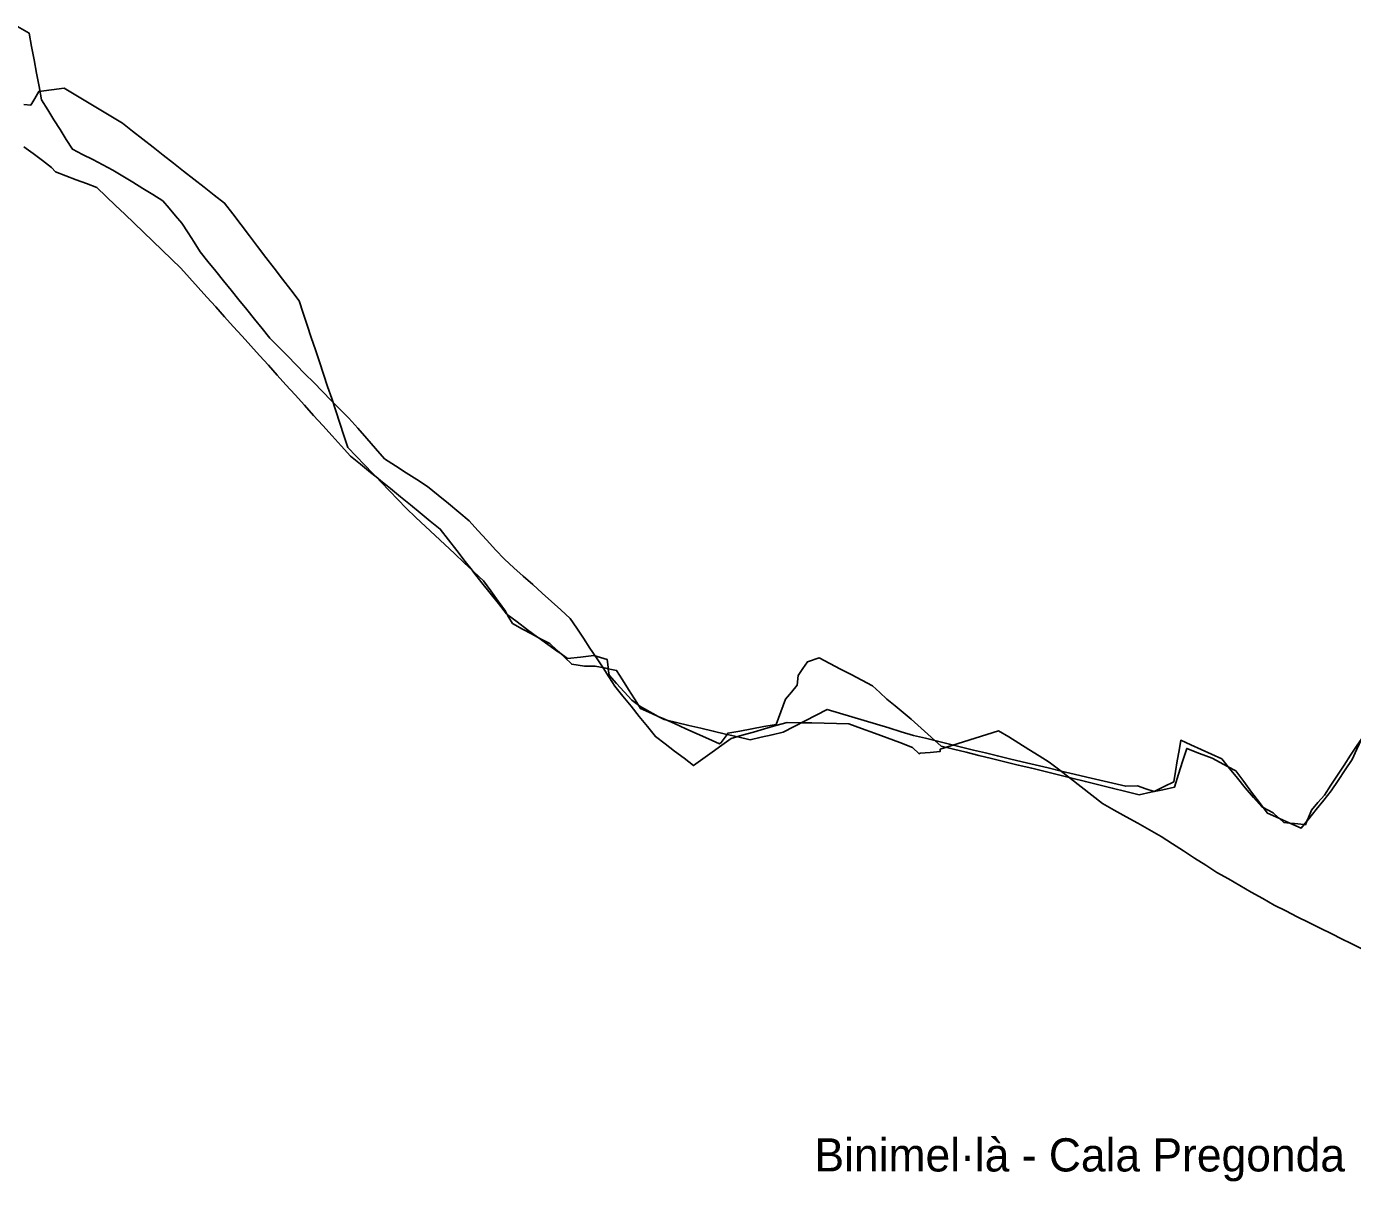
# Model space of a CAD drawing. Extents: x 574867 to 611521, y 4411908 to 4435758.
# Drawn here: x 589134 to 589613.3, y 4433897.6 to 4434315.2 of the extents above; entities that cross this region are included whole.
import ezdxf

# ---------------------------------------------------------------- set-up
doc = ezdxf.new("R2010")
doc.units = 0
doc.layers.add('Eqüestre', color=7, linetype='Continuous')

msp = doc.modelspace()

# ---------------------------------------------------------------- linework, layer by layer
at = {"layer": 'Eqüestre'}
for points in [[(589130.6652, 4434315.2055), (589134.9074, 4434312.813), (589135.8001, 4434307.9835), (589136.6928, 4434303.1539), (589137.5855, 4434298.3244), (589138.4782, 4434293.4948), (589139.3709, 4434288.6653), (589141.6137, 4434285.0949), (589143.8565, 4434281.5245), (589146.0994, 4434277.9541), (589148.3422, 4434274.3838), (589150.585, 4434270.8134), (589154.2325, 4434268.9413), (589157.88, 4434267.0692), (589161.5276, 4434265.1971), (589165.1751, 4434263.325), (589168.7841, 4434261.1028), (589172.393, 4434258.8806), (589176.002, 4434256.6584), (589179.611, 4434254.4361), (589183.22, 4434252.2139), (589185.5267, 4434249.5028), (589187.8334, 4434246.7916), (589190.1401, 4434244.0805), (589192.3417, 4434240.628), (589194.5434, 4434237.1756), (589196.7451, 4434233.7231), (589199.5441, 4434230.253), (589202.3432, 4434226.783), (589205.1422, 4434223.3129), (589207.9412, 4434219.8428), (589210.7403, 4434216.3727), (589213.5393, 4434212.9026), (589216.3383, 4434209.4325), (589219.1374, 4434205.9624), (589221.9364, 4434202.4923), (589225.102, 4434199.2856), (589228.2677, 4434196.0788), (589231.4333, 4434192.8721), (589234.5989, 4434189.6653), (589237.7646, 4434186.4586), (589240.9302, 4434183.2518), (589244.0958, 4434180.045), (589247.2615, 4434176.8383), (589250.4271, 4434173.6315), (589253.6694, 4434169.9508), (589256.9117, 4434166.2701), (589260.154, 4434162.5894), (589263.3963, 4434158.9087), (589267.286, 4434156.4012), (589271.1757, 4434153.8937), (589275.0653, 4434151.3862), (589278.955, 4434148.8787), (589282.7023, 4434145.7867), (589286.4495, 4434142.6947), (589290.1968, 4434139.6028), (589293.944, 4434136.5108), (589297.1415, 4434133.0239), (589300.3389, 4434129.5369), (589303.5363, 4434126.0499), (589306.7337, 4434122.563), (589310.1332, 4434119.5105), (589313.5327, 4434116.4581), (589316.9322, 4434113.4057), (589320.3317, 4434110.3532), (589323.7312, 4434107.3008), (589327.1307, 4434104.2484), (589330.5302, 4434101.196), (589332.8926, 4434097.627), (589335.255, 4434094.0581), (589337.6173, 4434090.4892), (589339.9797, 4434086.9203), (589342.3421, 4434083.3513), (589344.4711, 4434080.0461), (589346.6, 4434076.7408), (589349.5435, 4434073.0899), (589352.487, 4434069.4391), (589355.4304, 4434065.7882), (589358.3739, 4434062.1373), (589361.3174, 4434058.4864), (589364.7606, 4434055.8627), (589368.2038, 4434053.2389), (589371.6471, 4434050.6152), (589375.0903, 4434047.9915), (589378.4738, 4434050.4458), (589381.8573, 4434052.9001), (589385.2408, 4434055.3544), (589388.6243, 4434057.8087), (589392.6714, 4434058.9664), (589396.7184, 4434060.1242), (589400.7655, 4434061.2819), (589404.8126, 4434062.4396), (589408.8597, 4434063.5974), (589413.3311, 4434063.4946), (589417.8025, 4434063.3919), (589422.2739, 4434063.2891), (589426.7453, 4434063.1863), (589431.2167, 4434063.0836), (589435.8264, 4434061.3839), (589440.4361, 4434059.6843), (589445.0457, 4434057.9846), (589449.6554, 4434056.2849), (589454.265, 4434054.5853), (589456.5955, 4434052.2815), (589457.0194, 4434052.5085), (589460.5992, 4434052.7727), (589464.1791, 4434053.0369), (589464.254, 4434053.9259), (589468.4695, 4434055.2633), (589472.6851, 4434056.6006), (589476.9007, 4434057.938), (589481.1163, 4434059.2754), (589485.3319, 4434060.6128), (589488.9927, 4434058.3469), (589492.6536, 4434056.0811), (589496.3145, 4434053.8152), (589499.9754, 4434051.5493), (589503.6363, 4434049.2835), (589507.4934, 4434046.2873), (589511.3506, 4434043.2911), (589515.2078, 4434040.2949), (589519.065, 4434037.2987), (589522.9222, 4434034.3025), (589527.1646, 4434031.9103), (589531.4071, 4434029.5181), (589535.6496, 4434027.1259), (589539.8921, 4434024.7337), (589544.1346, 4434022.3415), (589548.1577, 4434019.7469), (589552.1808, 4434017.1523), (589556.2039, 4434014.5577), (589560.227, 4434011.9631), (589564.2501, 4434009.3685), (589568.39, 4434006.9973), (589572.5299, 4434004.6261), (589576.6698, 4434002.255), (589580.8097, 4433999.8838), (589584.9496, 4433997.5126), (589589.1203, 4433995.4304), (589593.2909, 4433993.3482), (589597.4615, 4433991.266), (589601.6322, 4433989.1839), (589605.8028, 4433987.1017), (589609.321, 4433985.367), (589612.8392, 4433983.6324), (589616.3573, 4433981.8977)], [(589132.9407, 4434286.9698), (589135.5028, 4434286.7223), (589136.9235, 4434289.2367), (589138.3442, 4434291.7511), (589142.9436, 4434292.3602), (589147.543, 4434292.9692), (589151.7529, 4434290.421), (589155.9629, 4434287.8728), (589160.1728, 4434285.3246), (589164.3828, 4434282.7764), (589168.5927, 4434280.2282), (589172.2863, 4434277.3409), (589175.9798, 4434274.4537), (589179.6734, 4434271.5664), (589183.367, 4434268.6791), (589187.0606, 4434265.7918), (589190.7541, 4434262.9046), (589194.4477, 4434260.0173), (589198.1413, 4434257.13), (589201.8348, 4434254.2427), (589205.5284, 4434251.3554), (589208.5224, 4434247.4313), (589211.5163, 4434243.5071), (589214.5102, 4434239.5829), (589217.5042, 4434235.6588), (589220.4981, 4434231.7346), (589223.4921, 4434227.8104), (589226.486, 4434223.8862), (589229.48, 4434219.9621), (589232.4739, 4434216.0379), (589233.9477, 4434211.6148), (589235.4214, 4434207.1918), (589236.8952, 4434202.7687), (589238.369, 4434198.3456), (589239.8428, 4434193.9225), (589241.3165, 4434189.4995), (589242.7903, 4434185.0764), (589244.2641, 4434180.6533), (589245.7379, 4434176.2303), (589247.2116, 4434171.8072), (589248.6854, 4434167.3841), (589250.1592, 4434162.961), (589253.1575, 4434159.8246), (589256.1557, 4434156.6881), (589259.154, 4434153.5516), (589260.3134, 4434152.3388)], [(589260.3134, 4434152.3388), (589258.2645, 4434154.0029), (589254.6566, 4434156.933), (589251.0487, 4434159.8632), (589247.7149, 4434163.5508), (589244.3811, 4434167.2384), (589241.0473, 4434170.926), (589237.7135, 4434174.6135), (589234.3798, 4434178.3011), (589231.046, 4434181.9887), (589227.7122, 4434185.6763), (589224.543, 4434189.1914), (589221.3737, 4434192.7064), (589218.2045, 4434196.2215), (589215.0353, 4434199.7366), (589211.866, 4434203.2517), (589208.6968, 4434206.7668), (589205.5276, 4434210.2818), (589202.3583, 4434213.7969), (589199.1891, 4434217.312), (589196.0199, 4434220.8271), (589192.8506, 4434224.3422), (589189.6814, 4434227.8572), (589186.3164, 4434231.0987), (589182.9513, 4434234.3401), (589179.5863, 4434237.5816), (589176.2212, 4434240.823), (589172.8562, 4434244.0644), (589169.4912, 4434247.3059), (589166.1261, 4434250.5473), (589162.7611, 4434253.7888), (589159.3961, 4434257.0302), (589155.6688, 4434258.4296), (589151.9415, 4434259.8289), (589148.2142, 4434261.2283), (589144.4869, 4434262.6277), (589143.0174, 4434264.2756), (589139.6826, 4434266.7619), (589136.3477, 4434269.2482), (589133.0129, 4434271.7345)], [(589260.3134, 4434152.3388), (589262.1523, 4434150.4152), (589265.1506, 4434147.2787), (589268.1488, 4434144.1422), (589271.1471, 4434141.0058), (589274.6406, 4434137.7304), (589278.1341, 4434134.4551), (589281.6276, 4434131.1798), (589285.1211, 4434127.9044), (589288.6146, 4434124.6291), (589292.1081, 4434121.3537), (589295.0524, 4434118.5933)], [(589295.0524, 4434118.5933), (589292.5634, 4434121.8087), (589289.5489, 4434125.703), (589286.5344, 4434129.5973), (589283.5198, 4434133.4916), (589279.9119, 4434136.4218), (589276.304, 4434139.3519), (589272.6961, 4434142.2821), (589269.0882, 4434145.2123), (589265.4803, 4434148.1425), (589261.8724, 4434151.0727), (589260.3134, 4434152.3388)], [(589295.0524, 4434118.5933), (589295.6016, 4434118.0784), (589299.0951, 4434114.803), (589301.7544, 4434111.134), (589304.4137, 4434107.4649), (589307.0729, 4434103.7959), (589307.7408, 4434102.6296)], [(589307.7408, 4434102.6296), (589307.5112, 4434102.8019), (589304.5383, 4434106.5413), (589301.5654, 4434110.2807), (589298.5925, 4434114.0201), (589295.5779, 4434117.9144), (589295.0524, 4434118.5933)], [(589307.7408, 4434102.6296), (589308.3359, 4434101.5905), (589309.5988, 4434099.3852), (589313.206, 4434097.3184), (589316.4966, 4434095.581), (589318.6479, 4434094.4451)], [(589318.6479, 4434094.4451), (589315.0852, 4434097.1185), (589311.2982, 4434099.9602), (589307.7408, 4434102.6296)], [(589318.6479, 4434094.4451), (589319.7872, 4434093.8435), (589323.0778, 4434092.1061), (589325.7232, 4434089.621), (589326.7034, 4434088.7002)], [(589326.7034, 4434088.7002), (589325.9266, 4434089.2533), (589322.3994, 4434091.7651), (589318.8722, 4434094.2768), (589318.6479, 4434094.4451)], [(589326.7034, 4434088.7002), (589328.3686, 4434087.1359), (589331.014, 4434084.6508), (589335.6291, 4434083.928), (589339.4675, 4434083.9731), (589343.3583, 4434083.1863), (589344.2336, 4434083.0094)], [(589344.2336, 4434083.0094), (589344.1647, 4434083.5289), (589343.7902, 4434086.3552), (589338.9966, 4434087.7419), (589334.2252, 4434087.2418), (589329.4538, 4434086.7416), (589326.7034, 4434088.7002)], [(589387.1664, 4434059.2787), (589387.4412, 4434059.6715), (589391.8039, 4434060.4722), (589396.1666, 4434061.2728), (589400.5292, 4434062.0735), (589404.8919, 4434062.8742), (589406.6296, 4434067.446), (589408.3672, 4434072.0179), (589410.4276, 4434074.5399), (589412.488, 4434077.0619), (589412.8726, 4434080.6187), (589414.5498, 4434083.0807), (589416.227, 4434085.5426), (589420.4762, 4434086.9248), (589424.3389, 4434084.9055), (589428.2016, 4434082.8862), (589432.0642, 4434080.8669), (589435.9269, 4434078.8476), (589439.7896, 4434076.8283), (589442.3773, 4434074.4166), (589444.965, 4434072.0048), (589447.8938, 4434069.5971), (589450.8227, 4434067.1894), (589453.7516, 4434064.7817), (589457.3444, 4434061.5307), (589460.9373, 4434058.2798), (589462.3367, 4434057.0135)], [(589344.2336, 4434083.0094), (589347.2491, 4434082.3995), (589349.4224, 4434078.9561), (589351.5956, 4434075.5126), (589353.7688, 4434072.0691), (589355.1543, 4434069.8738)], [(589355.1543, 4434069.8738), (589352.7508, 4434071.5853), (589350.0136, 4434074.6244), (589347.2764, 4434077.6634), (589344.5392, 4434080.7025), (589344.2336, 4434083.0094)], [(589355.1543, 4434069.8738), (589355.9421, 4434068.6256), (589360.0218, 4434066.8023), (589362.3012, 4434065.7836)], [(589362.3012, 4434065.7836), (589360.3564, 4434066.8459), (589356.2781, 4434069.0736), (589355.1543, 4434069.8738)], [(589362.3012, 4434065.7836), (589364.1016, 4434064.979), (589365.4342, 4434064.3834)], [(589365.4342, 4434064.3834), (589364.4348, 4434064.6182), (589362.3012, 4434065.7836)], [(589462.3367, 4434057.0135), (589458.9198, 4434057.849), (589454.5885, 4434058.908), (589450.1245, 4434060.251), (589445.6604, 4434061.594), (589441.1963, 4434062.937), (589436.7322, 4434064.2799), (589432.2681, 4434065.6229), (589427.8041, 4434066.9659), (589423.34, 4434068.3089), (589419.3762, 4434066.2363), (589415.4124, 4434064.1637), (589411.4486, 4434062.091), (589407.4848, 4434060.0184), (589403.4858, 4434059.1203), (589399.4869, 4434058.2221), (589395.4879, 4434057.324), (589391.0518, 4434058.366), (589387.1664, 4434059.2787)], [(589365.4342, 4434064.3834), (589368.1813, 4434063.1557), (589372.261, 4434061.3324), (589376.3408, 4434059.5091), (589380.4205, 4434057.6858), (589384.5002, 4434055.8625), (589385.0921, 4434056.3135), (589387.1664, 4434059.2787)], [(589387.1664, 4434059.2787), (589386.6156, 4434059.408), (589382.1795, 4434060.4501), (589377.7433, 4434061.4921), (589373.3072, 4434062.5341), (589368.871, 4434063.5761), (589365.4342, 4434064.3834)], [(589568.3716, 4434047.5227), (589566.0168, 4434050.4526), (589562.3074, 4434052.1295), (589558.598, 4434053.8064), (589554.8886, 4434055.4833), (589551.1792, 4434057.1602), (589550.5623, 4434053.4063), (589549.9454, 4434049.6525), (589549.3285, 4434045.8986), (589548.7117, 4434042.1448), (589545.1495, 4434040.3821), (589541.5872, 4434038.6194), (589538.5467, 4434039.6382), (589535.5062, 4434040.6569), (589531.328, 4434040.4967), (589526.6514, 4434041.601), (589521.9748, 4434042.7053), (589517.2982, 4434043.8096), (589512.6216, 4434044.9139), (589507.945, 4434046.0182), (589503.2684, 4434047.1225), (589498.5918, 4434048.2269), (589493.9152, 4434049.3312), (589489.2386, 4434050.4355), (589484.9073, 4434051.4945), (589480.5761, 4434052.5536), (589476.2448, 4434053.6127), (589471.9136, 4434054.6718), (589467.5823, 4434055.7308), (589463.2511, 4434056.7899), (589462.3367, 4434057.0135)], [(589462.3367, 4434057.0135), (589464.5301, 4434055.0288), (589469.0859, 4434053.9169), (589473.6417, 4434052.8049), (589478.1976, 4434051.693), (589482.7534, 4434050.5811), (589487.6068, 4434049.3869), (589492.4603, 4434048.1927), (589497.3137, 4434046.9985), (589502.1672, 4434045.8044), (589507.0206, 4434044.6102), (589511.8741, 4434043.416), (589516.7275, 4434042.2218), (589521.5809, 4434041.0277), (589526.4344, 4434039.8335), (589531.2878, 4434038.6393), (589536.1413, 4434037.4451), (589540.3961, 4434038.3464), (589544.651, 4434039.2476), (589548.9058, 4434040.1489), (589550.3862, 4434044.8287), (589551.8666, 4434049.5086), (589553.347, 4434054.1885), (589557.932, 4434052.4109), (589562.517, 4434050.6333), (589566.8094, 4434048.3527), (589568.3716, 4434047.5227)], [(589616.6344, 4434057.843), (589614.9836, 4434055.3411), (589612.6089, 4434051.7423), (589610.2343, 4434048.1435), (589607.8597, 4434044.5446), (589605.485, 4434040.9458), (589603.1104, 4434037.3469), (589600.7541, 4434034.5994), (589598.3979, 4434031.8518), (589597.3198, 4434029.2304), (589596.7846, 4434027.929)], [(589596.7846, 4434027.929), (589597.4323, 4434028.7322), (589600.1439, 4434032.0945), (589602.8554, 4434035.4568), (589605.567, 4434038.8191), (589608.0814, 4434042.6231), (589610.5958, 4434046.4271), (589613.1102, 4434050.2311), (589614.8156, 4434053.9145), (589616.5209, 4434057.598), (589616.6344, 4434057.843)], [(589568.3716, 4434047.5227), (589571.1017, 4434046.0721), (589573.962, 4434042.2483), (589576.8224, 4434038.4244), (589579.6827, 4434034.6006), (589580.9942, 4434032.8473)], [(589580.9942, 4434032.8473), (589580.5537, 4434033.0845), (589577.5276, 4434036.4901), (589574.5016, 4434039.8957), (589571.6734, 4434043.4146), (589568.8451, 4434046.9336), (589568.3716, 4434047.5227)], [(589580.9942, 4434032.8473), (589582.543, 4434030.7767), (589586.6022, 4434028.9744), (589586.8588, 4434028.8605)], [(589586.8588, 4434028.8605), (589586.529, 4434029.1586), (589584.5888, 4434030.9119), (589580.9942, 4434032.8473)], [(589586.8588, 4434028.8605), (589590.6365, 4434027.1833)], [(589590.6365, 4434027.1833), (589588.4691, 4434027.4053), (589586.8588, 4434028.8605)], [(589596.7846, 4434027.929), (589596.2417, 4434026.6089), (589595.7598, 4434026.6583)], [(589595.7598, 4434026.6583), (589596.7846, 4434027.929)], [(589590.6365, 4434027.1833), (589590.6615, 4434027.1722), (589594.7207, 4434025.3699), (589595.7598, 4434026.6583)], [(589595.7598, 4434026.6583), (589592.3554, 4434027.0071), (589590.6365, 4434027.1833)]]:
    msp.add_lwpolyline(points, dxfattribs=at)

# ---------------------------------------------------------------- texts
msp.add_text('Binimel·là - Cala Pregonda', height=12, dxfattribs=at).set_placement((589418.7969, 4433901.2404))

doc.saveas('drawing.dxf')
